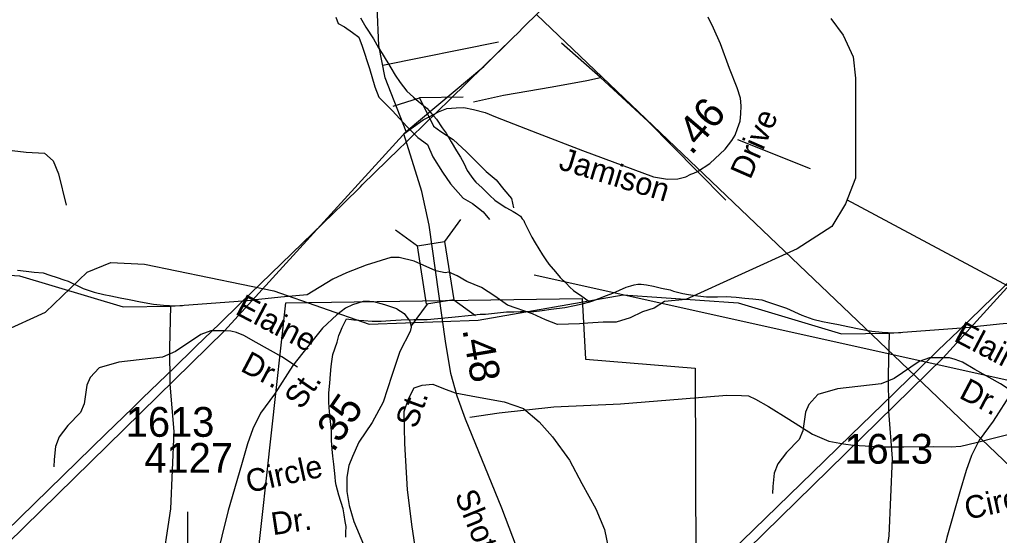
# Model space of a CAD drawing. Extents: x 2169602 to 2449496, y 721995 to 810662.
# Drawn here: x 2392905 to 2397017, y 771901 to 774064 of the extents above; entities that cross this region are included whole.
import ezdxf

# ---------------------------------------------------------------- set-up
doc = ezdxf.new("R2010")
doc.units = 0
doc.layers.add('Default', color=7, linetype='Continuous')

msp = doc.modelspace()

# ---------------------------------------------------------------- linework, layer by layer
at = {"layer": 'Default'}
for p, q in [((2394913.9, 773969.7), (2394428.9, 773871.2)), ((2395343.3, 773820.8), (2395178.4, 773965)), ((2394472.6, 773700.7), (2394582.8, 773736.4)), ((2394766.7, 773739.1), (2394582.8, 773736.4)), ((2394582.8, 773736.4), (2394641.7, 773616.7)), ((2395918.2, 773561), (2396221.9, 773439.1)), ((2395749.1, 773427.6), (2395868.5, 773307.4)), ((2394754.9, 773225.4), (2394688.4, 773133.8)), ((2394482.5, 773182.2), (2394574.1, 773115.7)), ((2395064.8, 772994), (2398022.8, 772336.6)), ((2393534.8, 772688.1), (2393538.9, 772861.7)), ((2393538.9, 772861.7), (2393898.1, 772888.6)), ((2394614.9, 772871.2), (2394548.4, 772779.6)), ((2394726.7, 772888.9), (2394818.3, 772822.4)), ((2396554.8, 772748.8), (2396913.9, 772775.8)), ((2396550.6, 772575.3), (2396554.8, 772748.8)), ((2393536.9, 772535), (2393534.8, 772688.1)), ((2396552.7, 772422.2), (2396550.6, 772575.3))]:
    msp.add_line(p, q, dxfattribs=at)
for points in [[(2386380.1, 765643.4), (2386857.9, 766106.2), (2386916.4, 766162.9), (2386960.4, 766205.5), (2388333.9, 767535.6), (2388482.6, 767665.6), (2388839.5, 768000.9), (2389171, 768336), (2391030.3, 770080.7), (2393764.7, 772758.1), (2394526.4, 773595), (2394852.5, 773868.2), (2394973.7, 773986.6), (2394998.1, 774010.6), (2395018.6, 774030.8), (2395083, 774094), (2395207.8, 774217.2), (2395509.9, 774514.3), (2395511.9, 774516.4), (2395846.4, 774839.9), (2396368, 775322.6), (2396469.9, 775429.5)], [(2389396, 765530.5), (2389873.7, 765993.4), (2389932.2, 766050), (2389976.3, 766092.7), (2391349.7, 767422.8), (2391498.4, 767552.8), (2391855.4, 767888.1), (2392186.8, 768223.2), (2394046.1, 769967.9), (2396780.6, 772645.2), (2397542.2, 773482.1), (2397868.3, 773755.4), (2397989.5, 773873.8), (2398013.9, 773897.7), (2398034.4, 773917.9), (2398098.8, 773981.2), (2398223.7, 774104.3), (2398525.7, 774401.5), (2398527.8, 774403.5), (2398862.2, 774727.1), (2399383.8, 775209.8), (2399485.8, 775316.7)], [(2392800.3, 774512.3), (2392804.8, 774357.9), (2392782.2, 774185.4), (2392773.1, 773699.7), (2392791.2, 773572.1), (2392850.2, 773517.7), (2392931.9, 773508.6), (2393009, 773504), (2393045.3, 773472.3), (2393068, 773417.8), (2393099.7, 773286.1)], [(2394526.4, 773595), (2394438.8, 773820), (2394412.7, 773955.1), (2394404.8, 774118.4), (2394404.8, 774242), (2394410, 774322.6), (2394429.4, 774415.8)], [(2391030.3, 770080.7), (2393764.7, 772758.1), (2394526.4, 773595), (2394852.5, 773868.2), (2394973.7, 773986.6), (2394998.1, 774010.6), (2395018.6, 774030.8), (2395083, 774094)], [(2392186.8, 768223.2), (2394046.1, 769967.9), (2396780.6, 772645.2), (2397542.2, 773482.1), (2397868.3, 773755.4), (2397989.5, 773873.8), (2398013.9, 773897.7), (2398034.4, 773917.9), (2398098.8, 773981.2), (2398223.7, 774104.3)], [(2392724.7, 771799.1), (2393266.8, 772326.6), (2393378.4, 772434.7), (2393421, 772476.1), (2393554.5, 772605.6), (2393568.2, 772618.9), (2393621.4, 772670.4), (2393640, 772688.4), (2393644.7, 772693.1), (2393744.6, 772789.9), (2393828.9, 772871.5), (2394265.2, 773294.8), (2394335.3, 773363.4), (2394343.1, 773370.9), (2394499.6, 773523.8), (2394523, 773546.6), (2394546.3, 773569.5), (2394547.6, 773570.6), (2394711.8, 773731.1), (2394852.5, 773868.3), (2394973.7, 773986.7), (2394998.1, 774010.6), (2395018.6, 774030.8), (2395083, 774094.1)], [(2410998.9, 759007.9), (2409859, 760053.1), (2407211.5, 762601.4), (2405778.5, 763946.8), (2405684, 764042.1), (2405083.2, 764574.5), (2404665, 764982.2), (2402074.2, 767418.4), (2399573.8, 769793.5), (2395074.1, 774085.3)], [(2396309.1, 774069.1), (2396360.9, 773998.4), (2396403.3, 773908.8), (2396412.7, 773819.3), (2396412.7, 773564.7), (2396412.7, 773399.7), (2396370.3, 773291.3), (2396313.8, 773197), (2396167.8, 773102.7), (2395701.4, 772890.6), (2395611.9, 772881.2), (2395568.5, 772853.9), (2395518.5, 772838.4), (2395467.6, 772813.4), (2395409, 772795.3), (2395353.9, 772794.5), (2395289.2, 772791), (2395253.9, 772788.4), (2395162.2, 772785.7), (2395112.3, 772804.3), (2395056.6, 772830), (2394952.5, 772867.1), (2394899.4, 772904.3), (2394843.4, 772940.4), (2394781.1, 772965.4), (2394741.3, 772989), (2394706.4, 773005.2), (2394690.2, 773002.7), (2394651.3, 773010.3), (2394560.2, 773050.9), (2394498.2, 773066.2), (2394463.3, 773066.2), (2394358.6, 773034.2), (2394277.2, 773002.2), (2394219.1, 772976.1), (2394111.5, 772909.2), (2394000.8, 772900), (2393881.9, 772886.8)], [(2394231.8, 774073.9), (2394242, 774047.9), (2394268.1, 774034), (2394302.2, 774010.3), (2394328.2, 773990.4), (2394342.5, 773952.5), (2394372.9, 773858.7), (2394395.4, 773782.8), (2394411.7, 773738.9), (2394469.9, 773681.3), (2394530.3, 773615.7), (2394576.6, 773570), (2394616.8, 773540.1), (2394638.9, 773488.3), (2394679.4, 773424.7), (2394713.6, 773374.8), (2394766, 773315.1), (2394806.1, 773293.3), (2394830.1, 773273.4), (2394850.2, 773257.6), (2394876.3, 773225.7)], [(2394335.7, 774071.2), (2394357.8, 774033), (2394390.2, 773983.4), (2394410.3, 773945.6), (2394426.3, 773921.6), (2394462.6, 773861.8), (2394481.1, 773831.8), (2394501.4, 773800), (2394529.2, 773764.1), (2394557.7, 773738.3), (2394579.5, 773720.4), (2394613.9, 773692.9), (2394633.6, 773670.8), (2394653.9, 773647.1), (2394678.5, 773610.9), (2394694.5, 773587.4), (2394716.5, 773551.2), (2394738.6, 773513.4), (2394754.8, 773487.8), (2394768.7, 773461.8), (2394782.9, 773431.6), (2394799.3, 773408.1), (2394811.2, 773392.1), (2394819.2, 773381.9), (2394845.4, 773358.1), (2394865.5, 773338.5), (2394877.6, 773326.5), (2394899.8, 773306.5), (2394917.6, 773294.5), (2394945.7, 773276.8), (2394964.2, 773266.7), (2394976.1, 773258.9), (2394990, 773251), (2395006.2, 773239.3), (2395014.4, 773229.1), (2395020.3, 773221.3), (2395024, 773213.1), (2395030.2, 773199.2), (2395040.4, 773179.3), (2395054.6, 773151.2), (2395068.9, 773127.6), (2395098.9, 773077.6), (2395113.4, 773055.9), (2395125.3, 773037.9), (2395153.6, 773006.1), (2395173.5, 772982.4), (2395197.9, 772958.4), (2395213.5, 772942.2), (2395229.9, 772928.4), (2395243.6, 772918.7), (2395258, 772908.8), (2395280.1, 772892.8), (2395298, 772880.8)], [(2394517.6, 773585.4), (2394599, 773643.4), (2394624.2, 773656.5), (2394662.2, 773677.1), (2394697.5, 773691), (2394737.5, 773694.5), (2394768.7, 773695.7), (2394809.1, 773687.7), (2394859, 773674), (2394901.9, 773657.1), (2395078.4, 773587.4), (2395266.8, 773515.8), (2395565.1, 773404.3), (2395624.2, 773394.4), (2395666.6, 773396.2), (2395700.8, 773405), (2395722, 773415.7), (2395733.8, 773420.2), (2395749.1, 773427.6), (2395802.1, 773460.1), (2395865.2, 773521.4), (2395894.5, 773557.5), (2395908.2, 773579.9), (2395918.1, 773607.3), (2395928.7, 773638.5), (2395931.2, 773669), (2395933.1, 773702), (2395929.9, 773734.4), (2395916.2, 773778.6), (2395884.2, 773858.9), (2395845.6, 773962.3), (2395816.6, 774028.9), (2395794.8, 774075)], [(2394809.6, 773719.5), (2394935.2, 773747.1), (2395139.6, 773782.4), (2395285.1, 773809.1), (2395343.3, 773820.8)], [(2395343.3, 773820.8), (2395542.9, 773636.5), (2395749.1, 773427.6)], [(2394641.7, 773616.7), (2394672.1, 773594.5), (2394724.4, 773560.7), (2394780.5, 773509.1), (2394863.1, 773427.6), (2394905.1, 773391.8), (2394937.5, 773351.9), (2394969.7, 773314.3), (2394977.9, 773274.3)], [(2394650.4, 773012.7), (2394623, 773202), (2394593.1, 773342.7), (2394517.6, 773585.4)], [(2398080.6, 767097), (2398111.6, 767572), (2398093.6, 767736.3), (2398174.8, 768180.8), (2398115.7, 768313.2), (2397956.6, 768460.8), (2397578.7, 768983.5), (2397502.6, 769142.5), (2397468.8, 769307.2), (2397483.8, 769592.3), (2397524.8, 769768.7), (2397562.7, 770424), (2397733.8, 771083.1), (2397698.7, 771451.2), (2397520.7, 771900.9), (2397383.8, 772566.4), (2397316.9, 772715.3), (2397115.8, 772913), (2396376.9, 773308.2)], [(2392529.2, 768564.8), (2393320.7, 769330), (2393853.2, 769846.7), (2394000, 769990), (2394609.8, 770585.3), (2395445, 771398.7), (2395740.5, 771686.2), (2396282.6, 772213.8), (2396394.2, 772321.9), (2396436.8, 772363.2), (2396570.3, 772492.8), (2396584.1, 772506), (2396637.2, 772557.6), (2396655.8, 772575.6), (2396660.6, 772580.2), (2396760.4, 772677.1), (2396844.7, 772758.7), (2397281, 773182)], [(2389165.3, 772638.3), (2389640.9, 772787), (2389997.9, 772950.3), (2390172, 773117.3), (2390271.8, 773158), (2390412.9, 773151.8), (2390955.9, 773039), (2391355.9, 772899.6), (2391813.8, 772916.5), (2392421.8, 773022.2), (2392904.9, 772989.4), (2393338.8, 772859.1), (2393538.9, 772861.7)], [(2392181.1, 772525.5), (2392656.7, 772674.2), (2393013.7, 772837.5), (2393187.8, 773004.5), (2393287.7, 773045.1), (2393428.7, 773038.9), (2393971.7, 772926.2), (2394371.8, 772786.8), (2394829.6, 772803.6), (2395437.6, 772909.3), (2395920.7, 772876.5), (2396354.6, 772746.3), (2396554.8, 772748.8)], [(2392895.9, 773013.2), (2392932.2, 773009.3), (2392965.8, 773005.4), (2393003.9, 773001.7), (2393031.6, 772991.8), (2393061.8, 772982), (2393090.1, 772972.4), (2393108.1, 772966.5), (2393172.1, 772936.9), (2393218.2, 772921), (2393258.4, 772911.3), (2393288.3, 772905.5), (2393326.3, 772897.8), (2393364.4, 772890), (2393412.6, 772880.3), (2393466.1, 772870.5), (2393508.4, 772866.6), (2393534.4, 772864.7), (2393586.5, 772863.3)], [(2395255.6, 771213.2), (2395150.4, 771442.3), (2395020.8, 771771.1), (2394928.7, 772015.2), (2394775.5, 772388.8), (2394740.6, 772484.7), (2394714.5, 772580.5), (2394692.7, 772715), (2394650.4, 773012.7)], [(2395298, 772880.8), (2395309.9, 772885.1), (2395336.1, 772894.9), (2395367.9, 772907.1), (2395393.7, 772917.4), (2395421.8, 772929.4), (2395449.7, 772941.8), (2395469.4, 772947.8), (2395483.4, 772951.8), (2395499.3, 772954.2), (2395513.5, 772954.1), (2395535.6, 772952.3), (2395565.2, 772946.2), (2395598, 772938.4), (2395635.7, 772930.7), (2395649.6, 772925), (2395688, 772915.1), (2395712, 772911.1), (2395751.8, 772905.5), (2395787.6, 772901.6), (2395833.6, 772902), (2395869.9, 772902.2), (2395911.7, 772900.4), (2395948, 772896.5), (2395981.6, 772892.6), (2396019.8, 772888.9), (2396047.5, 772879), (2396077.6, 772869.1), (2396105.9, 772859.6), (2396123.9, 772853.7), (2396187.9, 772824.1), (2396234, 772808.2), (2396274.2, 772798.4), (2396304.2, 772792.7), (2396342.1, 772785), (2396380.2, 772777.2), (2396428.4, 772767.4), (2396482, 772757.7), (2396524.2, 772753.7), (2396550.2, 772751.8), (2396602.3, 772750.5)], [(2392316.5, 770137.1), (2393720.9, 770149.5), (2394021.5, 772875.9), (2395265.6, 772894.5), (2395279.9, 772640.6), (2395740.1, 772601.9), (2395746.2, 770941.8), (2396246.1, 770850.2), (2396253.7, 770315.9), (2396391.9, 770030.6), (2396460.4, 769741.7), (2396355.6, 769433.5), (2396385.6, 769182.3), (2396358.5, 768790.4), (2395702.6, 768512), (2395691.7, 767254.8), (2395679.8, 766410.9)], [(2394487.9, 772851.1), (2394437.6, 772868.4), (2394390.7, 772881), (2394372.5, 772882.5), (2394347, 772882.2), (2394301.5, 772867.6), (2394272.3, 772853.9), (2394236.2, 772826.5), (2394176.4, 772770.4), (2394114.1, 772693.2), (2394051.2, 772612.9), (2393974.9, 772493.4), (2393915.8, 772413.7), (2393883.4, 772348.3), (2393861, 772285.4), (2393835.5, 772196.3), (2393780.4, 772005.2), (2393648.4, 771472.2), (2393585.5, 771231.2), (2393578.6, 771162.7), (2393584.2, 771145.3), (2393606, 771128.5), (2393655.2, 771112.9), (2393878.2, 771057.7)], [(2394276.6, 772809), (2394306.8, 772805.2), (2394349, 772801.6), (2394384.9, 772799.9), (2394422.6, 772799.8), (2394461, 772802.2), (2394506.7, 772804.5), (2394559, 772806.8), (2394614.8, 772806.9), (2394718.5, 772815.5), (2394800.7, 772824.2), (2394838.3, 772828.2), (2394860.6, 772828.5), (2394910.4, 772834.8), (2394948.6, 772838.7), (2394978.7, 772839), (2395006.4, 772839.3), (2395026.5, 772839.6), (2395062.2, 772839.8), (2395098.1, 772843.7), (2395136.2, 772850.1), (2395192.4, 772856.2), (2395234.2, 772864.5), (2395266, 772872.6), (2395298, 772880.8)], [(2394487.9, 772851.1), (2394518.4, 772831.5), (2394542.8, 772799.1), (2394545.3, 772788.5), (2394548.4, 772774.8), (2394543.4, 772756.1), (2394500.9, 772671.5), (2394467.3, 772571.2), (2394430.9, 772459.7), (2394384.8, 772373.8), (2394328.8, 772291.6), (2394301.7, 772231.2), (2394286.7, 772193.9), (2394278.6, 772145.3), (2394278.6, 772084.3), (2394288, 772026.4), (2394307.6, 771959.1), (2394347.4, 771863.2), (2394384.8, 771777.3), (2394393.5, 771737.5), (2394396.6, 771697), (2394393.5, 771599.8), (2394373, 771265.5), (2394371.1, 771122.9)], [(2394273.7, 771893.5), (2394273.7, 771913.4), (2394275.6, 771937.4), (2394271.7, 771959.5), (2394267.4, 771987.4), (2394263.3, 772011.5), (2394244.8, 772069), (2394232.7, 772111), (2394230.7, 772127.2), (2394228.4, 772146.9), (2394223.9, 772199.1), (2394219.8, 772233), (2394215.9, 772262.9), (2394213.9, 772298.8), (2394213.3, 772339.1), (2394209.4, 772379), (2394204.9, 772419.1), (2394202.6, 772458.7), (2394202.6, 772498.9), (2394206.3, 772538.9), (2394210, 772576.9), (2394212, 772609), (2394215.5, 772630.8), (2394219.8, 772659), (2394237.5, 772711), (2394245, 772739.1), (2394253, 772759), (2394258.8, 772773.1), (2394276.6, 772809)], [(2397503.7, 772738.3), (2397453.4, 772755.6), (2397406.5, 772768.2), (2397388.3, 772769.7), (2397362.8, 772769.4), (2397317.4, 772754.7), (2397288.1, 772741.1), (2397252, 772713.7), (2397192.2, 772657.6), (2397129.9, 772580.4), (2397067, 772500.1), (2396990.8, 772380.5), (2396931.6, 772300.8), (2396899.2, 772235.4), (2396876.8, 772172.6), (2396851.3, 772083.5), (2396796.2, 771892.4), (2396664.2, 771359.3), (2396601.3, 771118.4), (2396594.4, 771049.9), (2396600, 771032.4), (2396621.8, 771015.6), (2396671, 771000.1), (2396894.1, 770944.8)], [(2397127.4, 772796.3), (2397016.6, 772787.2), (2396897.7, 772774)], [(2393764.7, 772758.1), (2393707.8, 772759.1), (2393664.8, 772743.5), (2393559.7, 772672), (2393504.6, 772648.7), (2393321.9, 772628), (2393239.3, 772603.9), (2393201.4, 772562.5), (2393187.1, 772530.9), (2393175.7, 772452.8), (2393160.1, 772415.9), (2393107.6, 772361.9), (2393070.8, 772313.7), (2393055.2, 772273.9), (2393049.5, 772218.6), (2393048.1, 772188.7)], [(2394070.7, 772606), (2394005.5, 772649.6), (2393898.1, 772709.3), (2393846.4, 772739.8), (2393814.6, 772751.8), (2393791.8, 772757.7), (2393764.7, 772758.1)], [(2396780.6, 772645.2), (2396723.6, 772646.2), (2396680.6, 772630.7), (2396575.5, 772559.2), (2396520.4, 772535.9), (2396337.8, 772515.2), (2396255.1, 772491.1), (2396217.2, 772449.7), (2396202.9, 772418), (2396191.6, 772340), (2396176, 772303), (2396123.5, 772249.1), (2396086.6, 772200.8), (2396071, 772161.1), (2396065.3, 772105.7), (2396063.9, 772075.9)], [(2397086.5, 772493.1), (2397021.3, 772536.8), (2396913.9, 772596.5), (2396862.2, 772627), (2396830.4, 772638.9), (2396807.7, 772644.9), (2396780.6, 772645.2)], [(2393155.7, 767525.4), (2392995.8, 767807.5), (2392909.7, 768232.4), (2392916.7, 768507.8), (2393376.8, 769643.3), (2393357.8, 769942.2), (2393179.8, 770500.1), (2393285.8, 771032.7), (2393457.8, 771475.3), (2393538.8, 772011.7), (2393552.8, 772336.1), (2393536.9, 772535)], [(2394574.5, 771788.5), (2394551.8, 771936.3), (2394532.8, 772092.3), (2394521.7, 772286.1), (2394519.1, 772420.1), (2394536.8, 772474.1), (2394560.5, 772520.3), (2394594.3, 772530.4), (2394638.4, 772534.7), (2394684.4, 772516.9), (2394732.5, 772499.1), (2394822.5, 772481.7), (2394938.6, 772460.3), (2395018.9, 772432.9), (2395085.1, 772377.2), (2395141.4, 772313.6), (2395212, 772216), (2395264.4, 772118.4), (2395323, 772012.8), (2395359.4, 771925), (2395402.7, 771715.2)], [(2394793.6, 772396.8), (2394917, 772415.4), (2395147.4, 772439.4), (2395427, 772452), (2395685.8, 772473.3), (2395872.5, 772488.6), (2395934.8, 772486.9), (2395964.3, 772485.8), (2395992.7, 772472.7), (2396047.3, 772441.1), (2396132.4, 772388.6), (2396231.8, 772325.9), (2396300.6, 772295.3), (2396361.8, 772284.4), (2396403.3, 772278.9), (2396531, 772271.8), (2396615.1, 772272.9), (2396738.5, 772274), (2396813.9, 772272.9), (2396855.4, 772275.1), (2396919.8, 772290.4), (2397090.1, 772334)], [(2396171.6, 767412.5), (2396011.6, 767694.7), (2395925.5, 768119.6), (2395932.5, 768395), (2396392.6, 769530.5), (2396373.6, 769829.3), (2396195.6, 770387.3), (2396301.6, 770919.9), (2396473.7, 771362.5), (2396554.7, 771898.8), (2396568.6, 772223.3), (2396552.7, 772422.2)], [(2393317.8, 770625.5), (2393467.4, 770715.5), (2393540.6, 770797.2), (2393578.3, 770883.1), (2393607.6, 771042.2), (2393611.8, 771272.6), (2393610.7, 771999.3)]]:
    msp.add_lwpolyline(points, dxfattribs=at)
msp.add_lwpolyline([(2394688.4, 773133.8), (2394727.2, 772889), (2394612.8, 772870.9), (2394574.1, 773115.7)], close=True, dxfattribs=at)

# ---------------------------------------------------------------- texts
for s, height, rotation, p in [('.46', 125, 49.4379, (2395724, 773491.7)), ('Drive', 95, 66.3904, (2395971, 773389.9)), ('Jamison', 95, 343.0006, (2395162.3, 773438)), ('Elaine', 95, 332.2311, (2393805.2, 772831.3)), ('Elaine', 95, 332.2311, (2396821, 772718.5)), ('.48', 125, 279.6888, (2394762.5, 772764.5)), ('Dr.', 95, 332.2311, (2393826.9, 772592.9)), ('St.', 95, 55.3623, (2394087.8, 772424.5)), ('Dr.', 95, 332.2311, (2396842.7, 772480)), ('.35', 125, 55.7131, (2394221.2, 772244.9)), ('St.', 95, 70.1417, (2394568.9, 772344.5)), ('Circle', 95, 12.3387, (2393865.7, 772078.6)), ('Circle', 95, 12.3387, (2396881.5, 771965.8)), ('Shotwell', 95, 292.1209, (2394729.2, 772070.2)), ('Dr.', 95, 8.512, (2393967.8, 771901.2))]:
    msp.add_text(s, height=height, rotation=rotation, dxfattribs=at).set_placement(p)
for s, p in [('1613', (2393350.3, 772314.3)), ('1613', (2396366.2, 772201.5)), ('4127', (2393428.5, 772163.4))]:
    msp.add_text(s, height=125, dxfattribs=at).set_placement(p)

doc.saveas('drawing.dxf')
